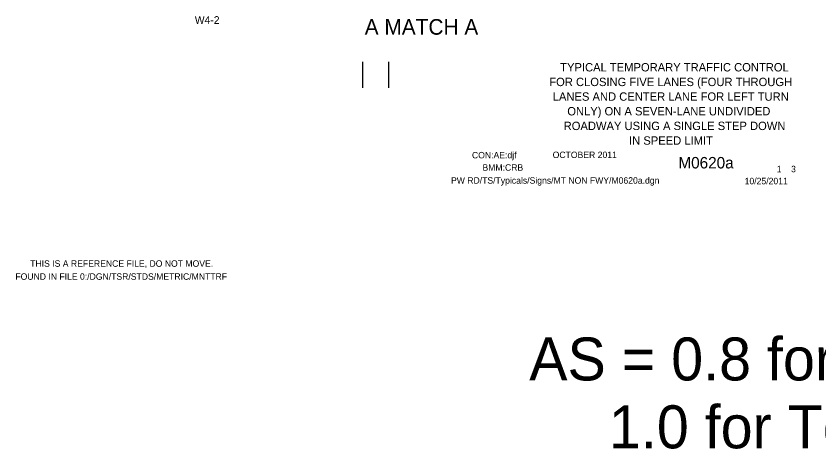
# Model space of a CAD drawing. Extents: x 20837 to 23689, y 414 to 2167.
# Drawn here: x 20837 to 21609, y 414 to 830 of the extents above; entities that cross this region are included whole.
import ezdxf

# ---------------------------------------------------------------- set-up
doc = ezdxf.new("R2010")
doc.units = 0
for name, color, linetype in [('BORDER_SIGNAL_WO', 7, 'Continuous'), ('PAVT_EDGE_EX', 7, 'Continuous'), ('SCRATCH_LEVEL_A', 7, 'Continuous'), ('TRAFFIC_SIGNS_PR', 7, 'Continuous'), ('TYPICAL_TEXT_DIMEN_PR', 7, 'Continuous')]:
    doc.layers.add(name, color=color, linetype=linetype)

msp = doc.modelspace()

# ---------------------------------------------------------------- linework, layer by layer
at = {"layer": 'PAVT_EDGE_EX'}
for points in [[(21170.09, 760.99), (21170.09, 785.99)], [(21170.09, 760.99), (21170.09, 785.99)], [(21195.09, 760.99), (21195.09, 785.99)], [(21195.09, 760.99), (21195.09, 785.99)]]:
    msp.add_lwpolyline(points, dxfattribs=at)

# ---------------------------------------------------------------- texts
at = {"layer": 'BORDER_SIGNAL_WO'}
for s, height, p in [('TYPICAL TEMPORARY TRAFFIC CONTROL', 8.0393, (21359.86, 776.88)), ('FOR CLOSING FIVE LANES (FOUR THROUGH', 8.0393, (21349.36, 762.78)), ('LANES AND CENTER LANE FOR LEFT TURN', 8.0393, (21352.69, 748.7)), ('ONLY) ON A SEVEN-LANE UNDIVIDED', 8.0393, (21366.67, 734.6)), ('ROADWAY USING A SINGLE STEP DOWN', 8.0393, (21363.19, 720.51)), ('IN SPEED LIMIT', 8.0393, (21426.07, 706.42)), ('CON:AE:djf', 6.2, (21275, 693.3)), ('    OCTOBER 2011    ', 6.2, (21343.39, 693.58)), ('BMM:CRB   ', 6.2, (21285.12, 681.42)), ('    M0620a   ', 11, (21457.17, 683.62)), (' 1    3 ', 6.2, (21565.76, 679.94)), ('PW RD/TS/Typicals/Signs/MT NON FWY/M0620a.dgn    ', 6.2, (21254.86, 668.96)), ('10/25/2011    ', 6.2, (21537.24, 668.38)), ('AS = 0.8 for Sign Cells', 41.2877, (21330.07, 479.79)), ('     1.0 for Text Cells', 41.2877, (21330.07, 414.51))]:
    msp.add_text(s, height=height, dxfattribs=at).set_placement(p)
at = {"layer": 'SCRATCH_LEVEL_A'}
for s, p in [('THIS IS A REFERENCE FILE, DO NOT MOVE.', (20850.17, 589.06)), ('FOUND IN FILE 0:/DGN/TSR/STDS/METRIC/MNTTRF', (20835.9, 576.56))]:
    msp.add_text(s, height=6.2, dxfattribs=at).set_placement(p)
at = {"layer": 'TRAFFIC_SIGNS_PR'}
msp.add_text('W4-2', height=7.44, dxfattribs=at).set_placement((21008.48, 822.57))
at = {"layer": 'TYPICAL_TEXT_DIMEN_PR'}
msp.add_text('A MATCH A', height=15, dxfattribs=at).set_placement((21171.85, 812.2))

doc.saveas('drawing.dxf')
